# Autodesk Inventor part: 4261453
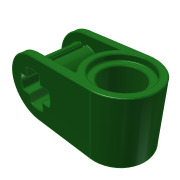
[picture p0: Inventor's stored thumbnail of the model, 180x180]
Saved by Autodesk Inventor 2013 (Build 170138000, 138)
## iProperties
Created: 2013-03
Part Number: 4261453
Material: Generic
Document SubType Name: Modeling
Designer: perblt
Density: 1 g/cm^3
Translation Standard: STEP AP203
FileName: 4261453
PreProcessor: PRO/ENGINEER BY PARAMETRIC TECHNOLOGY CORPORATION, 2010370
PostProcessor: Build: 138, Release: 2013 RTM - Date: Thu 03/01/2012
Sent Units: millimeter
Uncertainty: 0.0024077289272319996
Author: perblt
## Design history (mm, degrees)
node "42614531"
fillet "Fillet1" dims "d2" = 0.1, "d3" = 0.1
node "4261453"
node "Base1"
